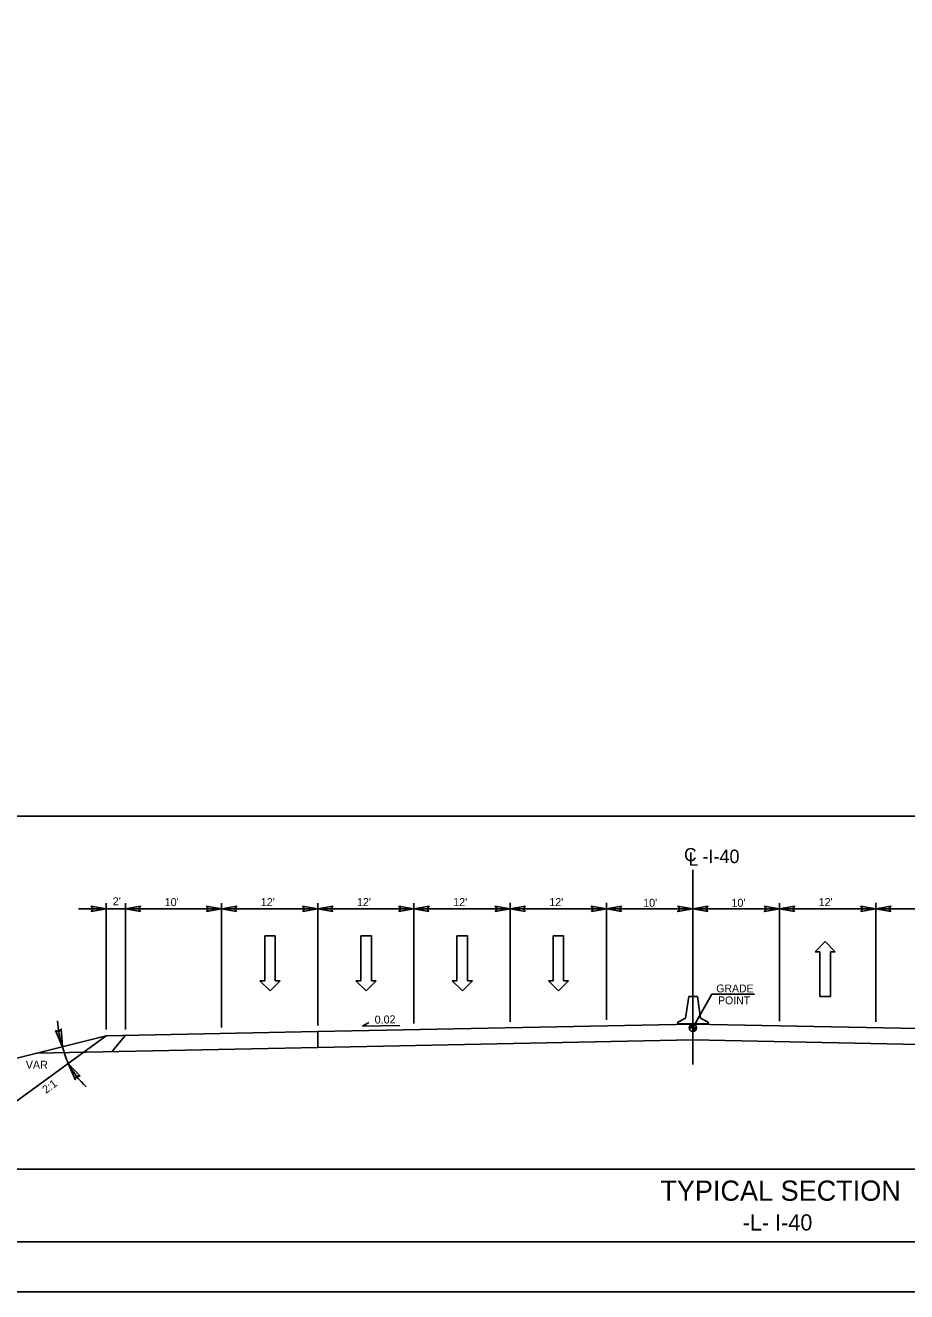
# Model space of a CAD drawing. Extents: x 1636954 to 1644154, y 841334 to 845582.
# Drawn here: x 1637865 to 1638748, y 841334 to 842602 of the extents above; entities that cross this region are included whole.
import ezdxf

# ---------------------------------------------------------------- set-up
doc = ezdxf.new("R2010")
doc.units = 0
for name, color, linetype in [('Default', 7, 'Continuous'), ('Prop Dimension', 7, 'Continuous'), ('Prop Dimension Text', 7, 'Continuous'), ('Prop PHM Legend CELL', 7, 'Continuous'), ('Scratch_Level_1', 7, 'Continuous'), ('Sheet Plan And Profile CELL', 7, 'Continuous'), ('Typical Grade Point Symbol CELL', 7, 'Continuous'), ('Typical Hinge Slope Interstate CELL', 7, 'Continuous'), ('Typical Pavement Slope CELL', 7, 'Continuous'), ('Typical Pavement Slope Information CELL', 7, 'Continuous'), ('Typical Text Centerline CELL', 7, 'Continuous'), ('Typical Text General CELL', 7, 'Continuous'), ('Typical Text Grade Point CELL', 7, 'Continuous'), ('Typical Text Label CELL', 7, 'Continuous')]:
    doc.layers.add(name, color=color, linetype=linetype)

msp = doc.modelspace()

# ---------------------------------------------------------------- linework, layer by layer
at = {"layer": 'Default'}
for p, q in [((1638526.2, 841607.8), (1638529.4, 841629.5)), ((1638529.4, 841629.5), (1638533.7, 841629.5)), ((1638538.1, 841629.5), (1638533.7, 841629.5)), ((1638541.2, 841607.8), (1638538.1, 841629.5))]:
    msp.add_line(p, q, dxfattribs=at)
for points in [[(1638541, 841602.2), (1638518.6, 841602.2), (1638518.6, 841603.9), (1638526.2, 841607.8)], [(1638526.4, 841602.2), (1638548.8, 841602.2), (1638548.8, 841603.9), (1638541.2, 841607.8)]]:
    msp.add_lwpolyline(points, dxfattribs=at)
for points in [[(1637895.4, 841595.4), (1637902.5, 841579.3), (1637901.2, 841597), (1637898.8, 841594.1)], [(1637920.3, 841549.8), (1637908.2, 841562.6), (1637915.3, 841546.4), (1637916.6, 841549.9)], [(1637920.3, 841549.8), (1637908.2, 841562.6), (1637915.3, 841546.4), (1637916.6, 841549.9)]]:
    msp.add_lwpolyline(points, close=True, dxfattribs=at)
at = {"layer": 'Prop Dimension'}
for p, q in [((1637946.3, 841596.6), (1637946.3, 841723.2)), ((1637965.5, 841596.6), (1637965.5, 841723.2)), ((1637965.5, 841596.6), (1637965.5, 841721.3)), ((1638061.8, 841598.5), (1638061.8, 841723.2)), ((1638158, 841600.5), (1638158, 841723.2)), ((1638254.3, 841602.4), (1638254.3, 841723.2)), ((1638350.7, 841604.3), (1638350.7, 841723.5)), ((1638447, 841606.2), (1638447, 841723.4)), ((1638620.3, 841604.7), (1638620.3, 841723.2)), ((1638716.7, 841604.3), (1638716.7, 841723.5)), ((1637918.6, 841717.3), (1637965.7, 841717.3)), ((1637965.7, 841717.3), (1638061.9, 841717.3)), ((1638061.9, 841717.3), (1638158.2, 841717.3)), ((1638158.2, 841717.3), (1638254.5, 841717.3)), ((1638254.5, 841717.3), (1638350.7, 841717.3)), ((1638350.7, 841717.3), (1638447, 841717.3)), ((1638447, 841717.3), (1638533.6, 841717.3)), ((1638533.6, 841717.3), (1638620.4, 841717.3)), ((1638620.4, 841717.3), (1638716.7, 841717.3)), ((1638716.7, 841717.3), (1638813, 841717.3)), ((1638104.9, 841645.3), (1638104.9, 841690.2)), ((1638104.9, 841690.2), (1638115.5, 841690.2)), ((1638115.5, 841690.2), (1638115.5, 841645.3)), ((1638201.1, 841645.3), (1638201.1, 841690.2)), ((1638201.1, 841690.2), (1638211.7, 841690.2)), ((1638211.7, 841690.2), (1638211.7, 841645.3)), ((1638297.4, 841645.3), (1638297.4, 841690.2)), ((1638297.4, 841690.2), (1638308, 841690.2)), ((1638308, 841690.2), (1638308, 841645.3)), ((1638393.7, 841645.3), (1638393.7, 841690.2)), ((1638393.7, 841690.2), (1638404.2, 841690.2)), ((1638404.2, 841690.2), (1638404.2, 841645.3)), ((1638666.1, 841684.5), (1638655.9, 841674.4)), ((1638676.1, 841674.4), (1638666.1, 841684.5)), ((1638655.9, 841674.4), (1638660.7, 841674.4)), ((1638660.7, 841674.4), (1638660.7, 841629.5)), ((1638671.3, 841629.5), (1638671.3, 841674.4)), ((1638671.3, 841674.4), (1638676.1, 841674.4)), ((1638110.3, 841635.2), (1638100.1, 841645.3)), ((1638100.1, 841645.3), (1638104.9, 841645.3)), ((1638120.3, 841645.3), (1638110.3, 841635.2)), ((1638115.5, 841645.3), (1638120.3, 841645.3)), ((1638206.6, 841635.2), (1638196.3, 841645.3)), ((1638196.3, 841645.3), (1638201.1, 841645.3)), ((1638216.5, 841645.3), (1638206.6, 841635.2)), ((1638211.7, 841645.3), (1638216.5, 841645.3)), ((1638302.9, 841635.2), (1638292.6, 841645.3)), ((1638292.6, 841645.3), (1638297.4, 841645.3)), ((1638312.8, 841645.3), (1638302.9, 841635.2)), ((1638308, 841645.3), (1638312.8, 841645.3)), ((1638399.1, 841635.2), (1638388.9, 841645.3)), ((1638388.9, 841645.3), (1638393.7, 841645.3)), ((1638409.1, 841645.3), (1638399.1, 841635.2)), ((1638404.2, 841645.3), (1638409.1, 841645.3)), ((1638660.7, 841629.5), (1638671.3, 841629.5))]:
    msp.add_line(p, q, dxfattribs=at)
for points in [[(1637931.2, 841714.7), (1637946.3, 841717.3), (1637931.1, 841720), (1637933.1, 841717.3)], [(1637980.5, 841714.7), (1637965.5, 841717.3), (1637980.6, 841720), (1637978.7, 841717.3)], [(1638046.7, 841714.7), (1638061.8, 841717.3), (1638046.7, 841720), (1638048.6, 841717.3)], [(1638076.8, 841714.7), (1638061.8, 841717.3), (1638076.9, 841720), (1638075, 841717.3)], [(1638143, 841714.7), (1638158, 841717.3), (1638142.9, 841720), (1638144.8, 841717.3)], [(1638173.1, 841714.7), (1638158, 841717.3), (1638173.1, 841720), (1638171.2, 841717.3)], [(1638239.3, 841714.7), (1638254.3, 841717.3), (1638239.2, 841720), (1638241.1, 841717.3)], [(1638269.3, 841714.7), (1638254.3, 841717.3), (1638269.4, 841720), (1638267.5, 841717.3)], [(1638335.7, 841714.7), (1638350.7, 841717.3), (1638335.6, 841720), (1638337.5, 841717.3)], [(1638365.8, 841714.7), (1638350.7, 841717.3), (1638365.8, 841720), (1638363.9, 841717.3)], [(1638432, 841714.7), (1638447, 841717.3), (1638431.9, 841720), (1638433.8, 841717.3)], [(1638462, 841714.7), (1638447, 841717.3), (1638462.1, 841720), (1638460.2, 841717.3)], [(1638518.5, 841719.9), (1638533.6, 841717.3), (1638518.4, 841714.6), (1638520.4, 841717.3)], [(1638548.6, 841714.7), (1638533.6, 841717.3), (1638548.7, 841720), (1638546.7, 841717.3)], [(1638605.2, 841719.9), (1638620.3, 841717.3), (1638605.2, 841714.6), (1638607.1, 841717.3)], [(1638635.3, 841714.7), (1638620.3, 841717.3), (1638635.4, 841720), (1638633.5, 841717.3)], [(1638701.7, 841714.7), (1638716.7, 841717.3), (1638701.6, 841720), (1638703.5, 841717.3)], [(1638731.7, 841714.7), (1638716.7, 841717.3), (1638731.8, 841720), (1638729.9, 841717.3)]]:
    msp.add_lwpolyline(points, close=True, dxfattribs=at)
at = {"layer": 'Prop PHM Legend CELL'}
msp.add_line((1637654.2, 841456.6), (1640851.7, 841456.6), dxfattribs=at)
msp.add_lwpolyline([(1637654.2, 841810.2), (1639599.4, 841810.2), (1639599.4, 841383.9), (1637654.2, 841383.9)], close=True, dxfattribs=at)
at = {"layer": 'Scratch_Level_1'}
msp.add_lwpolyline([(1636954.2, 841333.9), (1636954.2, 844733.9), (1644154.2, 844733.9), (1644154.2, 841333.9)], close=True, dxfattribs=at)
at = {"layer": 'Sheet Plan And Profile CELL'}
msp.add_lwpolyline([(1637004.2, 841383.9), (1637004.2, 844683.9), (1644104.2, 844683.9), (1644104.2, 841383.9)], close=True, dxfattribs=at)
at = {"layer": 'Typical Grade Point Symbol CELL'}
for p, q in [((1638530, 841598.2), (1638533.6, 841598.2)), ((1638533.6, 841598.2), (1638533.6, 841601.8)), ((1638533.6, 841594.6), (1638533.6, 841598.2)), ((1638537.1, 841598.2), (1638533.6, 841598.2)), ((1638533.6, 841598.2), (1638533.6, 841594.6))]:
    msp.add_line(p, q, dxfattribs=at)
for points in [[(1638530, 841598.7), (1638530, 841598.2)], [(1638530.1, 841599.3), (1638530.1, 841598.2)], [(1638530.1, 841599.1), (1638530.1, 841598.2)], [(1638530.2, 841599.5), (1638530.2, 841598.2)], [(1638530.3, 841599.7), (1638530.3, 841598.2)], [(1638530.4, 841600), (1638530.4, 841598.2)], [(1638530.4, 841599.8), (1638530.4, 841598.2)], [(1638530.5, 841600.1), (1638530.5, 841598.2)], [(1638530.6, 841600.3), (1638530.6, 841598.2)], [(1638530.6, 841600.2), (1638530.6, 841598.2)], [(1638530.7, 841600.4), (1638530.7, 841598.2)], [(1638530.8, 841600.5), (1638530.8, 841598.2)], [(1638530.9, 841600.6), (1638530.9, 841598.2)], [(1638530.9, 841600.6), (1638530.9, 841598.2)], [(1638531, 841600.7), (1638531, 841598.2)], [(1638531.1, 841600.8), (1638531.1, 841598.2)], [(1638531.2, 841600.9), (1638531.2, 841598.2)], [(1638531.2, 841600.9), (1638531.2, 841598.2)], [(1638531.3, 841601), (1638531.3, 841598.2)], [(1638531.4, 841601.1), (1638531.4, 841598.2)], [(1638531.4, 841601), (1638531.4, 841598.2)], [(1638531.5, 841601.1), (1638531.5, 841598.2)], [(1638531.6, 841601.2), (1638531.6, 841598.2)], [(1638531.7, 841601.3), (1638531.7, 841598.2)], [(1638531.7, 841601.2), (1638531.7, 841598.2)], [(1638531.8, 841601.3), (1638531.8, 841598.2)], [(1638531.9, 841601.4), (1638531.9, 841598.2)], [(1638531.9, 841601.4), (1638531.9, 841598.2)], [(1638532, 841601.4), (1638532, 841598.2)], [(1638532.1, 841601.5), (1638532.1, 841598.2)], [(1638532.2, 841601.5), (1638532.2, 841598.2)], [(1638532.2, 841601.5), (1638532.2, 841598.2)], [(1638532.3, 841601.6), (1638532.3, 841598.2)], [(1638532.4, 841601.6), (1638532.4, 841598.2)], [(1638532.4, 841601.6), (1638532.4, 841598.2)], [(1638532.5, 841601.6), (1638532.5, 841598.2)], [(1638532.6, 841601.6), (1638532.6, 841598.2)], [(1638532.7, 841601.7), (1638532.7, 841598.2)], [(1638532.7, 841601.7), (1638532.7, 841598.2)], [(1638532.8, 841601.7), (1638532.8, 841598.2)], [(1638532.9, 841601.7), (1638532.9, 841598.2)], [(1638532.9, 841601.7), (1638532.9, 841598.2)], [(1638533, 841601.7), (1638533, 841598.2)], [(1638533.1, 841601.7), (1638533.1, 841598.2)], [(1638533.2, 841601.8), (1638533.2, 841598.2)], [(1638533.2, 841601.8), (1638533.2, 841598.2)], [(1638533.3, 841601.8), (1638533.3, 841598.2)], [(1638533.4, 841601.8), (1638533.4, 841598.2)], [(1638533.4, 841601.8), (1638533.4, 841598.2)], [(1638533.5, 841601.8), (1638533.5, 841601.8), (1638533.5, 841598.2)], [(1638533.6, 841598.2), (1638533.6, 841594.6), (1638533.6, 841594.6)], [(1638533.7, 841598.2), (1638533.7, 841594.6)], [(1638533.7, 841598.2), (1638533.7, 841594.6)], [(1638533.8, 841598.2), (1638533.8, 841594.6)], [(1638533.9, 841598.2), (1638533.9, 841594.6)], [(1638534, 841598.2), (1638534, 841594.6)], [(1638534, 841598.2), (1638534, 841594.6)], [(1638534.1, 841598.2), (1638534.1, 841594.7)], [(1638534.2, 841598.2), (1638534.2, 841594.7)], [(1638534.3, 841598.2), (1638534.3, 841594.7)], [(1638534.3, 841598.2), (1638534.3, 841594.7)], [(1638534.4, 841598.2), (1638534.4, 841594.7)], [(1638534.5, 841598.2), (1638534.5, 841594.7)], [(1638534.5, 841598.2), (1638534.5, 841594.7)], [(1638534.6, 841598.2), (1638534.6, 841594.8)], [(1638534.7, 841598.2), (1638534.7, 841594.8)], [(1638534.8, 841598.2), (1638534.8, 841594.8)], [(1638534.8, 841598.2), (1638534.8, 841594.8)], [(1638534.9, 841598.2), (1638534.9, 841594.9)], [(1638535, 841598.2), (1638535, 841594.9)], [(1638535, 841598.2), (1638535, 841594.9)], [(1638535.1, 841598.2), (1638535.1, 841595)], [(1638535.2, 841598.2), (1638535.2, 841595)], [(1638535.3, 841598.2), (1638535.3, 841595.1)], [(1638535.3, 841598.2), (1638535.3, 841595)], [(1638535.4, 841598.2), (1638535.4, 841595.1)], [(1638535.5, 841598.2), (1638535.5, 841595.2)], [(1638535.5, 841598.2), (1638535.5, 841595.2)], [(1638535.6, 841598.2), (1638535.6, 841595.3)], [(1638535.7, 841598.2), (1638535.7, 841595.3)], [(1638535.8, 841598.2), (1638535.8, 841595.4)], [(1638535.8, 841598.2), (1638535.8, 841595.4)], [(1638535.9, 841598.2), (1638535.9, 841595.5)], [(1638536, 841598.2), (1638536, 841595.6)], [(1638536, 841598.2), (1638536, 841595.5)], [(1638536.1, 841598.2), (1638536.1, 841595.7)], [(1638536.2, 841598.2), (1638536.2, 841595.8)], [(1638536.3, 841598.2), (1638536.3, 841595.9)], [(1638536.3, 841598.2), (1638536.3, 841595.8)], [(1638536.4, 841598.2), (1638536.4, 841596)], [(1638536.5, 841598.2), (1638536.5, 841596.2)], [(1638536.5, 841598.2), (1638536.5, 841596.1)], [(1638536.6, 841598.2), (1638536.6, 841596.3)], [(1638536.7, 841598.2), (1638536.7, 841596.5)], [(1638536.8, 841598.2), (1638536.8, 841596.7)], [(1638536.8, 841598.2), (1638536.8, 841596.6)], [(1638536.9, 841598.2), (1638536.9, 841596.9)], [(1638537, 841598.2), (1638537, 841597.1)], [(1638537.1, 841598.2), (1638537.1, 841597.8)], [(1638537.1, 841598.2), (1638537.1, 841597.4)]]:
    msp.add_lwpolyline(points, dxfattribs=at)
msp.add_circle((1638533.6, 841598.2), 3.59, dxfattribs=at)
for start, end in [(90.0093, 180.0093), (270.0093, 0.0093)]:
    msp.add_arc((1638533.6, 841598.2), 3.59, start, end, dxfattribs=at)
at = {"layer": 'Typical Hinge Slope Interstate CELL'}
for p, q in [((1637946.3, 841590.3), (1637808, 841555.7)), ((1637946.3, 841590.3), (1637825.1, 841502.1)), ((1637965.5, 841590.7), (1637951.7, 841574.3))]:
    msp.add_line(p, q, dxfattribs=at)
for centre, start, end in [((1637994.1, 841610.3), 182.9343, 198.686), ((1637992.7, 841609.6), 209.0778, 226.6941), ((1637992.7, 841609.6), 209.0778, 226.6941)]:
    msp.add_arc(centre, 96.8, start, end, dxfattribs=at)
msp.add_ellipse((1637948.8, 841634.5), major_axis=(-14.9, -95.6), ratio=0.5, start_param=5.403228, end_param=5.638322, dxfattribs=at)
at = {"layer": 'Typical Pavement Slope CELL'}
for p, q in [((1637946.3, 841590.3), (1638158, 841594.5)), ((1638158, 841594.5), (1638533.6, 841602)), ((1638158, 841578.5), (1638158, 841594.5)), ((1638909.1, 841594.5), (1638533.6, 841602)), ((1638158, 841578.5), (1638533.6, 841586)), ((1638807.6, 841580.5), (1638533.6, 841586)), ((1637876.5, 841572.8), (1638158, 841578.5))]:
    msp.add_line(p, q, dxfattribs=at)
at = {"layer": 'Typical Pavement Slope Information CELL'}
for q in [(1638209.2, 841603.6), (1638240.3, 841600.5)]:
    msp.add_line((1638202.9, 841599.8), q, dxfattribs=at)
at = {"layer": 'Typical Text Centerline CELL'}
for p, q in [((1638533.6, 841725.2), (1638533.6, 841756.5)), ((1638533.6, 841561.3), (1638533.6, 841725.2))]:
    msp.add_line(p, q, dxfattribs=at)
at = {"layer": 'Typical Text Grade Point CELL'}
for q in [(1638533.6, 841598.2), (1638595.1, 841631.8)]:
    msp.add_line((1638552.6, 841631.8), q, dxfattribs=at)

# ---------------------------------------------------------------- texts
at = {"layer": 'Prop Dimension Text'}
msp.add_text('VAR', height=8.02, dxfattribs=at).set_placement((1637865.7, 841557.2))
msp.add_text('2:1', height=8.02, rotation=36.0298, dxfattribs=at).set_placement((1637885.9, 841531.9))
at = {"layer": 'Typical Pavement Slope Information CELL'}
for s, p in [("2'", (1637952.8, 841720.9)), ("10'", (1638004.8, 841720.1)), ("12'", (1638101, 841720.1)), ("12'", (1638197.3, 841720.1)), ("12'", (1638293.6, 841720.1)), ("12'", (1638389.8, 841720.1)), ("10'", (1638483.8, 841719.4)), ("10'", (1638572.2, 841719.4)), ("12'", (1638659.5, 841720.1))]:
    msp.add_text(s, height=8.02, dxfattribs=at).set_placement(p)
msp.add_text('0.02', height=8.02, rotation=1.1457, dxfattribs=at).set_placement((1638215.1, 841602.3))
at = {"layer": 'Typical Text Centerline CELL'}
for s, height, rotation, p in [('C', 13.1, 0.0443, (1638524.7, 841765.1)), ('L', 13.2, 359.9912, (1638529.1, 841760.6)), ('-I-40', 13.5, 359.9417, (1638543.1, 841763.2))]:
    msp.add_text(s, height=height, rotation=rotation, dxfattribs=at).set_placement(p)
at = {"layer": 'Typical Text General CELL'}
msp.add_text('-L- I-40', height=16.2, dxfattribs=at).set_placement((1638583.4, 841395.2))
at = {"layer": 'Typical Text Grade Point CELL'}
for s, p in [('GRADE', (1638557, 841633.7)), ('POINT', (1638558.8, 841621.8))]:
    msp.add_text(s, height=7.85, rotation=359.9998, dxfattribs=at).set_placement(p)
at = {"layer": 'Typical Text Label CELL'}
msp.add_text('TYPICAL SECTION', height=20.25, dxfattribs=at).set_placement((1638501, 841425))

doc.saveas('drawing.dxf')
